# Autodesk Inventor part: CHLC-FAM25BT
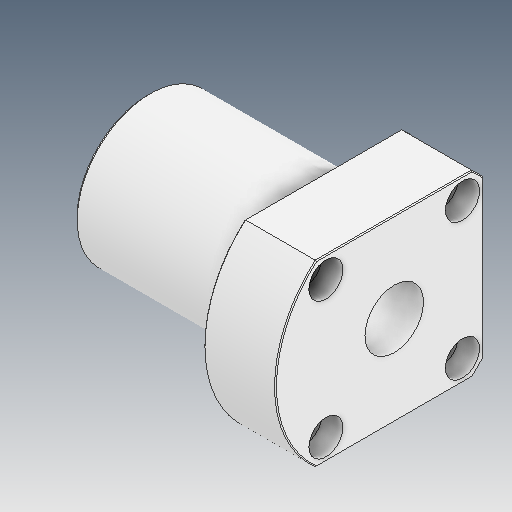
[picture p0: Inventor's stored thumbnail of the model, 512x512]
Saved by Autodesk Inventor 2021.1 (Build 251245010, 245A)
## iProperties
Created: 2021-05
Part Number: CHLC-FAM25BT
Material: Ogólny
Document SubType Name: Modeling
Designer: user
Density: 1 g/cm^3
Appearance: Domyślna
Author: user
Revision Number: ÈÎºÎ
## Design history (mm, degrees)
feature "Í¹Ì¨-À­Éì1"
node "Bryła1"
